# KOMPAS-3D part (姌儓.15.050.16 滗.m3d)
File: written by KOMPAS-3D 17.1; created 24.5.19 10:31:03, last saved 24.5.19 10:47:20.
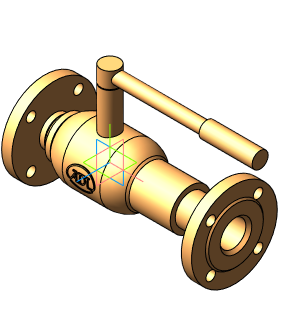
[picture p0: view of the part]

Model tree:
1. Операция без истории:1  (labels: Сталь 20  ГОСТ 1050-2013)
